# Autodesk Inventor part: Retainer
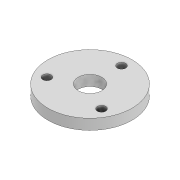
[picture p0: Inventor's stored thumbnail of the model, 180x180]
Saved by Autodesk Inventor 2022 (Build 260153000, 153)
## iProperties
Created: 2019-03
Part Number: Retainer
Material: Generic
Document SubType Name: Modeling
Designer: LENOVO-CADCIM
Density: 1 g/cm^3
Appearance: Default
Author: LENOVO-CADCIM
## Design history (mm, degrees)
sketch "Sketch1" dims "d1" = 150
  geometry: C1 r 100 at (0, 0); 3 further points
  constraints: 2 coincident, 1 centre point, 1 vertical alignment, 2 other
  dimensions: "d0" = 200 diameter of C1
extrude "Extrusion1" new body sketch "Sketch1" stored distance "d2" = 25; taper "d3" = 0 deg
sketch "Sketch2"
  geometry: L1 (0, 0)-(0, 174.732); C1 r 10 at (0, 75); A1 r 75 centre (0, 0) between (0, 75) and (0, 75); 1 further point
  constraints: 2 centre point, 2 coincident, 2 end point, 2 point on circle, 1 point on line, 1 vertical
  dimensions: "d4" = 150 diameter of A1; "d18" = 20 diameter of C1
sketch "Sketch3"
  geometry: C1 r 28 at (0, 0); 1 further point
  constraints: 1 centre point, 1 coincident
  dimensions: "d15" = 56 diameter of C1
extrude "Extrusion2" cut sketch "Sketch3" distance "d16" = 25; taper "d17" = 0 deg
extrude "Extrusion3" cut sketch "Sketch2" distance "d19" = 112.75; taper "d20" = 0 deg
pattern_circular "Circular Pattern2" dims angle "d22" = 360 deg
body "Solid1"
